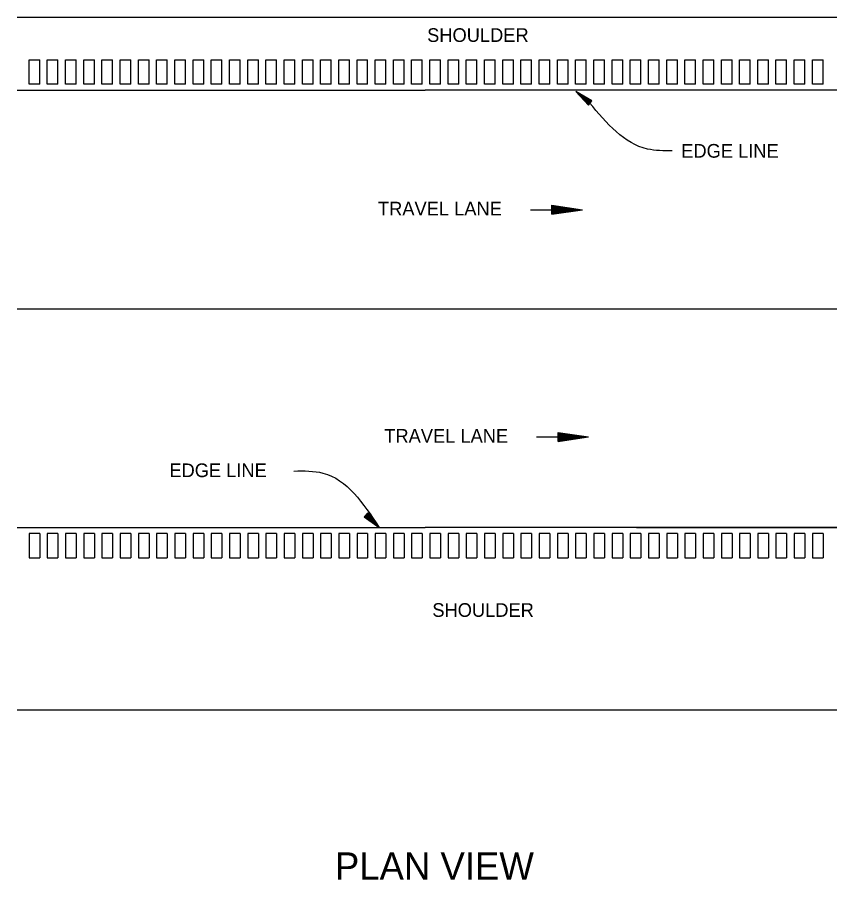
# Model space of a CAD drawing. Extents: x 1931522 to 1935523, y 600380 to 605075.
# Drawn here: x 1932731.4 to 1933091.3, y 600475.1 to 600853.7 of the extents above; entities that cross this region are included whole.
import ezdxf

# ---------------------------------------------------------------- set-up
doc = ezdxf.new("R2010")
doc.units = 0
doc.layers.add('Default', color=7, linetype='Continuous')

msp = doc.modelspace()

# ---------------------------------------------------------------- linework, layer by layer
at = {"layer": 'Default'}
for p, q in [((1932731.37, 600853.72), (1933091.26, 600853.72)), ((1932736.57, 600824.38), (1932736.57, 600835.02)), ((1932736.57, 600835.02), (1932741.25, 600835.02)), ((1932741.25, 600824.38), (1932741.25, 600835.02)), ((1932744.57, 600824.38), (1932744.57, 600835.02)), ((1932744.57, 600835.02), (1932749.25, 600835.02)), ((1932749.25, 600824.38), (1932749.25, 600835.02)), ((1932752.57, 600824.38), (1932752.57, 600835.02)), ((1932752.57, 600835.02), (1932757.25, 600835.02)), ((1932757.25, 600824.38), (1932757.25, 600835.02)), ((1932760.57, 600824.38), (1932760.57, 600835.02)), ((1932760.57, 600835.02), (1932765.25, 600835.02)), ((1932765.25, 600824.38), (1932765.25, 600835.02)), ((1932768.57, 600824.38), (1932768.57, 600835.02)), ((1932768.57, 600835.02), (1932773.25, 600835.02)), ((1932773.25, 600824.38), (1932773.25, 600835.02)), ((1932776.57, 600824.38), (1932776.57, 600835.02)), ((1932776.57, 600835.02), (1932781.25, 600835.02)), ((1932781.25, 600824.38), (1932781.25, 600835.02)), ((1932784.57, 600824.38), (1932784.57, 600835.02)), ((1932784.57, 600835.02), (1932789.25, 600835.02)), ((1932789.25, 600824.38), (1932789.25, 600835.02)), ((1932792.57, 600824.38), (1932792.57, 600835.02)), ((1932792.57, 600835.02), (1932797.25, 600835.02)), ((1932797.25, 600824.38), (1932797.25, 600835.02)), ((1932800.57, 600824.38), (1932800.57, 600835.02)), ((1932800.57, 600835.02), (1932805.25, 600835.02)), ((1932805.25, 600824.38), (1932805.25, 600835.02)), ((1932808.57, 600824.38), (1932808.57, 600835.02)), ((1932808.57, 600835.02), (1932813.25, 600835.02)), ((1932813.25, 600824.38), (1932813.25, 600835.02)), ((1932816.57, 600824.38), (1932816.57, 600835.02)), ((1932816.57, 600835.02), (1932821.26, 600835.02)), ((1932821.26, 600824.38), (1932821.26, 600835.02)), ((1932824.58, 600824.38), (1932824.58, 600835.02)), ((1932824.58, 600835.02), (1932829.26, 600835.02)), ((1932829.26, 600824.38), (1932829.26, 600835.02)), ((1932832.58, 600824.38), (1932832.58, 600835.02)), ((1932832.58, 600835.02), (1932837.26, 600835.02)), ((1932837.26, 600824.38), (1932837.26, 600835.02)), ((1932840.58, 600824.38), (1932840.58, 600835.02)), ((1932840.58, 600835.02), (1932845.26, 600835.02)), ((1932845.26, 600824.38), (1932845.26, 600835.02)), ((1932848.58, 600824.38), (1932848.58, 600835.02)), ((1932848.58, 600835.02), (1932853.26, 600835.02)), ((1932853.26, 600824.38), (1932853.26, 600835.02)), ((1932856.58, 600824.38), (1932856.58, 600835.02)), ((1932856.58, 600824.38), (1932856.58, 600835.02)), ((1932856.58, 600835.02), (1932861.26, 600835.02)), ((1932861.26, 600824.38), (1932861.26, 600835.02)), ((1932864.58, 600824.38), (1932864.58, 600835.02)), ((1932864.58, 600835.02), (1932869.26, 600835.02)), ((1932869.26, 600824.38), (1932869.26, 600835.02)), ((1932872.58, 600824.38), (1932872.58, 600835.02)), ((1932872.58, 600835.02), (1932877.26, 600835.02)), ((1932877.26, 600824.38), (1932877.26, 600835.02)), ((1932880.58, 600824.38), (1932880.58, 600835.02)), ((1932880.58, 600835.02), (1932885.26, 600835.02)), ((1932885.26, 600824.38), (1932885.26, 600835.02)), ((1932888.58, 600824.38), (1932888.58, 600835.02)), ((1932888.58, 600835.02), (1932893.26, 600835.02)), ((1932893.26, 600824.38), (1932893.26, 600835.02)), ((1932896.58, 600824.38), (1932896.58, 600835.02)), ((1932896.58, 600835.02), (1932901.26, 600835.02)), ((1932901.26, 600824.38), (1932901.26, 600835.02)), ((1932904.58, 600824.38), (1932904.58, 600835.02)), ((1932904.58, 600835.02), (1932909.26, 600835.02)), ((1932909.26, 600824.38), (1932909.26, 600835.02)), ((1932912.58, 600824.38), (1932912.58, 600835.02)), ((1932912.58, 600835.02), (1932917.26, 600835.02)), ((1932917.26, 600824.38), (1932917.26, 600835.02)), ((1932920.58, 600824.38), (1932920.58, 600835.02)), ((1932920.58, 600835.02), (1932925.26, 600835.02)), ((1932925.26, 600824.38), (1932925.26, 600835.02)), ((1932928.58, 600824.38), (1932928.58, 600835.02)), ((1932928.58, 600835.02), (1932933.26, 600835.02)), ((1932933.26, 600824.38), (1932933.26, 600835.02)), ((1932936.58, 600824.38), (1932936.58, 600835.02)), ((1932936.58, 600835.02), (1932941.26, 600835.02)), ((1932941.26, 600824.38), (1932941.26, 600835.02)), ((1932944.58, 600824.38), (1932944.58, 600835.02)), ((1932944.58, 600835.02), (1932949.26, 600835.02)), ((1932949.26, 600824.38), (1932949.26, 600835.02)), ((1932952.58, 600824.38), (1932952.58, 600835.02)), ((1932952.58, 600835.02), (1932957.26, 600835.02)), ((1932957.26, 600824.38), (1932957.26, 600835.02)), ((1932960.58, 600824.38), (1932960.58, 600835.02)), ((1932960.58, 600835.02), (1932965.26, 600835.02)), ((1932965.26, 600824.38), (1932965.26, 600835.02)), ((1932968.58, 600824.38), (1932968.58, 600835.02)), ((1932968.58, 600835.02), (1932973.26, 600835.02)), ((1932973.26, 600824.38), (1932973.26, 600835.02)), ((1932976.58, 600824.38), (1932976.58, 600835.02)), ((1932976.58, 600835.02), (1932981.26, 600835.02)), ((1932981.26, 600824.38), (1932981.26, 600835.02)), ((1932984.58, 600824.38), (1932984.58, 600835.02)), ((1932984.58, 600835.02), (1932989.26, 600835.02)), ((1932989.26, 600824.38), (1932989.26, 600835.02)), ((1932992.58, 600824.38), (1932992.58, 600835.02)), ((1932992.58, 600835.02), (1932997.26, 600835.02)), ((1932997.26, 600824.38), (1932997.26, 600835.02)), ((1933000.58, 600824.38), (1933000.58, 600835.02)), ((1933000.58, 600835.02), (1933005.26, 600835.02)), ((1933005.26, 600824.38), (1933005.26, 600835.02)), ((1933008.58, 600824.38), (1933008.58, 600835.02)), ((1933008.58, 600835.02), (1933013.26, 600835.02)), ((1933013.26, 600824.38), (1933013.26, 600835.02)), ((1933016.58, 600824.38), (1933016.58, 600835.02)), ((1933016.58, 600835.02), (1933021.26, 600835.02)), ((1933021.26, 600824.38), (1933021.26, 600835.02)), ((1933024.58, 600824.38), (1933024.58, 600835.02)), ((1933024.58, 600835.02), (1933029.26, 600835.02)), ((1933029.26, 600824.38), (1933029.26, 600835.02)), ((1933032.58, 600824.38), (1933032.58, 600835.02)), ((1933032.58, 600835.02), (1933037.26, 600835.02)), ((1933037.26, 600824.38), (1933037.26, 600835.02)), ((1933040.58, 600824.38), (1933040.58, 600835.02)), ((1933040.58, 600835.02), (1933045.26, 600835.02)), ((1933045.26, 600824.38), (1933045.26, 600835.02)), ((1933048.58, 600824.38), (1933048.58, 600835.02)), ((1933048.58, 600835.02), (1933053.26, 600835.02)), ((1933053.26, 600824.38), (1933053.26, 600835.02)), ((1933056.58, 600824.38), (1933056.58, 600835.02)), ((1933056.58, 600835.02), (1933061.26, 600835.02)), ((1933061.26, 600824.38), (1933061.26, 600835.02)), ((1933064.58, 600824.38), (1933064.58, 600835.02)), ((1933064.58, 600835.02), (1933069.26, 600835.02)), ((1933069.26, 600824.38), (1933069.26, 600835.02)), ((1933072.58, 600824.38), (1933072.58, 600835.02)), ((1933072.58, 600835.02), (1933077.26, 600835.02)), ((1933077.26, 600824.38), (1933077.26, 600835.02)), ((1933080.58, 600824.38), (1933080.58, 600835.02)), ((1933080.58, 600835.02), (1933085.26, 600835.02)), ((1933085.26, 600824.38), (1933085.26, 600835.02)), ((1932741.25, 600824.38), (1932736.57, 600824.38)), ((1932749.25, 600824.38), (1932744.57, 600824.38)), ((1932757.25, 600824.38), (1932752.57, 600824.38)), ((1932765.25, 600824.38), (1932760.57, 600824.38)), ((1932773.25, 600824.38), (1932768.57, 600824.38)), ((1932781.25, 600824.38), (1932776.57, 600824.38)), ((1932789.25, 600824.38), (1932784.57, 600824.38)), ((1932797.25, 600824.38), (1932792.57, 600824.38)), ((1932805.25, 600824.38), (1932800.57, 600824.38)), ((1932813.25, 600824.38), (1932808.57, 600824.38)), ((1932821.26, 600824.38), (1932816.57, 600824.38)), ((1932829.26, 600824.38), (1932824.58, 600824.38)), ((1932837.26, 600824.38), (1932832.58, 600824.38)), ((1932845.26, 600824.38), (1932840.58, 600824.38)), ((1932853.26, 600824.38), (1932848.58, 600824.38)), ((1932861.26, 600824.38), (1932856.58, 600824.38)), ((1932869.26, 600824.38), (1932864.58, 600824.38)), ((1932877.26, 600824.38), (1932872.58, 600824.38)), ((1932885.26, 600824.38), (1932880.58, 600824.38)), ((1932893.26, 600824.38), (1932888.58, 600824.38)), ((1932901.26, 600824.38), (1932896.58, 600824.38)), ((1932909.26, 600824.38), (1932904.58, 600824.38)), ((1932917.26, 600824.38), (1932912.58, 600824.38)), ((1932925.26, 600824.38), (1932920.58, 600824.38)), ((1932933.26, 600824.38), (1932928.58, 600824.38)), ((1932941.26, 600824.38), (1932936.58, 600824.38)), ((1932949.26, 600824.38), (1932944.58, 600824.38)), ((1932957.26, 600824.38), (1932952.58, 600824.38)), ((1932965.26, 600824.38), (1932960.58, 600824.38)), ((1932973.26, 600824.38), (1932968.58, 600824.38)), ((1932981.26, 600824.38), (1932976.58, 600824.38)), ((1932989.26, 600824.38), (1932984.58, 600824.38)), ((1932997.26, 600824.38), (1932992.58, 600824.38)), ((1933005.26, 600824.38), (1933000.58, 600824.38)), ((1933013.26, 600824.38), (1933008.58, 600824.38)), ((1933021.26, 600824.38), (1933016.58, 600824.38)), ((1933029.26, 600824.38), (1933024.58, 600824.38)), ((1933037.26, 600824.38), (1933032.58, 600824.38)), ((1933045.26, 600824.38), (1933040.58, 600824.38)), ((1933053.26, 600824.38), (1933048.58, 600824.38)), ((1933061.26, 600824.38), (1933056.58, 600824.38)), ((1933069.26, 600824.38), (1933064.58, 600824.38)), ((1933077.26, 600824.38), (1933072.58, 600824.38)), ((1933085.26, 600824.38), (1933080.58, 600824.38)), ((1932731.37, 600821.72), (1932910.48, 600821.72)), ((1933091.26, 600821.72), (1932910.48, 600821.72)), ((1932982.2, 600815.16), (1932976.7, 600821.1)), ((1932983.7, 600817.04), (1932976.7, 600821.1)), ((1932982.32, 600815.32), (1932977.74, 600820.26)), ((1932983.58, 600816.88), (1932977.74, 600820.26)), ((1932983.44, 600816.72), (1932978.82, 600819.42)), ((1932982.46, 600815.48), (1932978.82, 600819.42)), ((1932982.58, 600815.64), (1932979.86, 600818.58)), ((1932983.32, 600816.56), (1932979.86, 600818.58)), ((1932983.18, 600816.4), (1932980.92, 600817.72)), ((1932982.7, 600815.8), (1932980.92, 600817.72)), ((1932983.06, 600816.24), (1932981.96, 600816.9)), ((1932982.82, 600815.96), (1932981.96, 600816.9)), ((1932982.2, 600815.16), (1932983.7, 600817.04)), ((1932966.16, 600771.22), (1932979.6, 600769.24)), ((1932966.16, 600767.22), (1932966.16, 600771.22)), ((1932966.16, 600770.9), (1932977.36, 600769.24)), ((1932966.16, 600770.56), (1932975.06, 600769.24)), ((1932966.16, 600770.22), (1932972.84, 600769.24)), ((1932966.16, 600769.88), (1932970.54, 600769.24)), ((1932956.72, 600769.24), (1932979.6, 600769.24)), ((1932966.16, 600769.56), (1932968.3, 600769.24)), ((1932966.16, 600767.22), (1932979.6, 600769.24)), ((1932966.16, 600768.58), (1932970.54, 600769.24)), ((1932966.16, 600767.88), (1932975.06, 600769.24)), ((1932966.16, 600767.54), (1932977.36, 600769.24)), ((1932966.16, 600768.22), (1932972.84, 600769.24)), ((1932966.16, 600768.9), (1932968.3, 600769.24)), ((1932731.37, 600725.72), (1933091.26, 600725.72)), ((1932968.86, 600671.52), (1932982.3, 600669.54)), ((1932968.86, 600667.52), (1932968.86, 600671.52)), ((1932959.42, 600669.54), (1932982.3, 600669.54)), ((1932968.86, 600671.2), (1932980.06, 600669.54)), ((1932968.86, 600670.86), (1932977.76, 600669.54)), ((1932968.86, 600670.52), (1932975.54, 600669.54)), ((1932968.86, 600670.18), (1932973.24, 600669.54)), ((1932968.86, 600669.86), (1932971, 600669.54)), ((1932968.86, 600667.52), (1932982.3, 600669.54)), ((1932968.86, 600668.88), (1932973.24, 600669.54)), ((1932968.86, 600668.18), (1932977.76, 600669.54)), ((1932968.86, 600667.84), (1932980.06, 600669.54)), ((1932968.86, 600668.52), (1932975.54, 600669.54)), ((1932968.86, 600669.2), (1932971, 600669.54)), ((1932885.38, 600636.22), (1932883.72, 600634.5)), ((1932883.72, 600634.5), (1932890.3, 600629.78)), ((1932883.86, 600634.64), (1932889.34, 600630.72)), ((1932884, 600634.78), (1932888.34, 600631.68)), ((1932884.14, 600634.92), (1932887.4, 600632.6)), ((1932884.28, 600635.06), (1932886.42, 600633.54)), ((1932884.42, 600635.22), (1932885.46, 600634.48)), ((1932884.68, 600635.48), (1932885.46, 600634.48)), ((1932884.82, 600635.62), (1932886.42, 600633.54)), ((1932884.96, 600635.78), (1932887.4, 600632.6)), ((1932885.1, 600635.92), (1932888.34, 600631.68)), ((1932885.24, 600636.06), (1932889.34, 600630.72)), ((1932885.38, 600636.22), (1932890.3, 600629.78)), ((1932731.37, 600629.72), (1932910.48, 600629.72)), ((1933091.26, 600629.72), (1932910.48, 600629.72)), ((1933003.38, 600629.72), (1933091.26, 600629.72)), ((1932741.25, 600627.06), (1932736.57, 600627.06)), ((1932736.57, 600627.06), (1932736.57, 600616.42)), ((1932741.25, 600627.06), (1932741.25, 600616.42)), ((1932749.25, 600627.06), (1932744.57, 600627.06)), ((1932744.57, 600627.06), (1932744.57, 600616.42)), ((1932749.25, 600627.06), (1932749.25, 600616.42)), ((1932757.25, 600627.06), (1932752.57, 600627.06)), ((1932752.57, 600627.06), (1932752.57, 600616.42)), ((1932757.25, 600627.06), (1932757.25, 600616.42)), ((1932765.25, 600627.06), (1932760.57, 600627.06)), ((1932760.57, 600627.06), (1932760.57, 600616.42)), ((1932765.25, 600627.06), (1932765.25, 600616.42)), ((1932773.25, 600627.06), (1932768.57, 600627.06)), ((1932768.57, 600627.06), (1932768.57, 600616.42)), ((1932773.25, 600627.06), (1932773.25, 600616.42)), ((1932781.25, 600627.06), (1932776.57, 600627.06)), ((1932776.57, 600627.06), (1932776.57, 600616.42)), ((1932781.25, 600627.06), (1932781.25, 600616.42)), ((1932789.25, 600627.06), (1932784.57, 600627.06)), ((1932784.57, 600627.06), (1932784.57, 600616.42)), ((1932789.25, 600627.06), (1932789.25, 600616.42)), ((1932797.25, 600627.06), (1932792.57, 600627.06)), ((1932792.57, 600627.06), (1932792.57, 600616.42)), ((1932797.25, 600627.06), (1932797.25, 600616.42)), ((1932805.25, 600627.06), (1932800.57, 600627.06)), ((1932800.57, 600627.06), (1932800.57, 600616.42)), ((1932805.25, 600627.06), (1932805.25, 600616.42)), ((1932813.25, 600627.06), (1932808.57, 600627.06)), ((1932808.57, 600627.06), (1932808.57, 600616.42)), ((1932813.25, 600627.06), (1932813.25, 600616.42)), ((1932821.26, 600627.06), (1932816.57, 600627.06)), ((1932816.57, 600627.06), (1932816.57, 600616.42)), ((1932821.26, 600627.06), (1932821.26, 600616.42)), ((1932829.26, 600627.06), (1932824.58, 600627.06)), ((1932824.58, 600627.06), (1932824.58, 600616.42)), ((1932829.26, 600627.06), (1932829.26, 600616.42)), ((1932837.26, 600627.06), (1932832.58, 600627.06)), ((1932832.58, 600627.06), (1932832.58, 600616.42)), ((1932837.26, 600627.06), (1932837.26, 600616.42)), ((1932845.26, 600627.06), (1932840.58, 600627.06)), ((1932840.58, 600627.06), (1932840.58, 600616.42)), ((1932845.26, 600627.06), (1932845.26, 600616.42)), ((1932853.26, 600627.06), (1932848.58, 600627.06)), ((1932848.58, 600627.06), (1932848.58, 600616.42)), ((1932853.26, 600627.06), (1932853.26, 600616.42)), ((1932861.26, 600627.06), (1932856.58, 600627.06)), ((1932856.58, 600627.06), (1932856.58, 600616.42)), ((1932861.26, 600627.06), (1932861.26, 600616.42)), ((1932869.26, 600627.06), (1932864.58, 600627.06)), ((1932864.58, 600627.06), (1932864.58, 600616.42)), ((1932869.26, 600627.06), (1932869.26, 600616.42)), ((1932877.26, 600627.06), (1932872.58, 600627.06)), ((1932872.58, 600627.06), (1932872.58, 600616.42)), ((1932877.26, 600627.06), (1932877.26, 600616.42)), ((1932885.26, 600627.06), (1932880.58, 600627.06)), ((1932880.58, 600627.06), (1932880.58, 600616.42)), ((1932885.26, 600627.06), (1932885.26, 600616.42)), ((1932893.26, 600627.06), (1932888.58, 600627.06)), ((1932888.58, 600627.06), (1932888.58, 600616.42)), ((1932893.26, 600627.06), (1932893.26, 600616.42)), ((1932901.26, 600627.06), (1932896.58, 600627.06)), ((1932896.58, 600627.06), (1932896.58, 600616.42)), ((1932901.26, 600627.06), (1932901.26, 600616.42)), ((1932909.26, 600627.06), (1932904.58, 600627.06)), ((1932904.58, 600627.06), (1932904.58, 600616.42)), ((1932909.26, 600627.06), (1932909.26, 600616.42)), ((1932917.26, 600627.06), (1932912.58, 600627.06)), ((1932912.58, 600627.06), (1932912.58, 600616.42)), ((1932917.26, 600627.06), (1932917.26, 600616.42)), ((1932925.26, 600627.06), (1932920.58, 600627.06)), ((1932920.58, 600627.06), (1932920.58, 600616.42)), ((1932925.26, 600627.06), (1932925.26, 600616.42)), ((1932933.26, 600627.06), (1932928.58, 600627.06)), ((1932928.58, 600627.06), (1932928.58, 600616.42)), ((1932933.26, 600627.06), (1932933.26, 600616.42)), ((1932941.26, 600627.06), (1932936.58, 600627.06)), ((1932936.58, 600627.06), (1932936.58, 600616.42)), ((1932941.26, 600627.06), (1932941.26, 600616.42)), ((1932949.26, 600627.06), (1932944.58, 600627.06)), ((1932944.58, 600627.06), (1932944.58, 600616.42)), ((1932949.26, 600627.06), (1932949.26, 600616.42)), ((1932957.26, 600627.06), (1932952.58, 600627.06)), ((1932952.58, 600627.06), (1932952.58, 600616.42)), ((1932957.26, 600627.06), (1932957.26, 600616.42)), ((1932965.26, 600627.06), (1932960.58, 600627.06)), ((1932960.58, 600627.06), (1932960.58, 600616.42)), ((1932965.26, 600627.06), (1932965.26, 600616.42)), ((1932973.26, 600627.06), (1932968.58, 600627.06)), ((1932968.58, 600627.06), (1932968.58, 600616.42)), ((1932973.26, 600627.06), (1932973.26, 600616.42)), ((1932981.26, 600627.06), (1932976.58, 600627.06)), ((1932976.58, 600627.06), (1932976.58, 600616.42)), ((1932981.26, 600627.06), (1932981.26, 600616.42)), ((1932989.26, 600627.06), (1932984.58, 600627.06)), ((1932984.58, 600627.06), (1932984.58, 600616.42)), ((1932989.26, 600627.06), (1932989.26, 600616.42)), ((1932997.26, 600627.06), (1932992.58, 600627.06)), ((1932992.58, 600627.06), (1932992.58, 600616.42)), ((1932997.26, 600627.06), (1932997.26, 600616.42)), ((1933005.26, 600627.06), (1933000.58, 600627.06)), ((1933000.58, 600627.06), (1933000.58, 600616.42)), ((1933005.26, 600627.06), (1933005.26, 600616.42)), ((1933013.26, 600627.06), (1933008.58, 600627.06)), ((1933008.58, 600627.06), (1933008.58, 600616.42)), ((1933013.26, 600627.06), (1933013.26, 600616.42)), ((1933021.26, 600627.06), (1933016.58, 600627.06)), ((1933016.58, 600627.06), (1933016.58, 600616.42)), ((1933021.26, 600627.06), (1933021.26, 600616.42)), ((1933029.26, 600627.06), (1933024.58, 600627.06)), ((1933024.58, 600627.06), (1933024.58, 600616.42)), ((1933029.26, 600627.06), (1933029.26, 600616.42)), ((1933037.26, 600627.06), (1933032.58, 600627.06)), ((1933032.58, 600627.06), (1933032.58, 600616.42)), ((1933037.26, 600627.06), (1933037.26, 600616.42)), ((1933045.26, 600627.06), (1933040.58, 600627.06)), ((1933040.58, 600627.06), (1933040.58, 600616.42)), ((1933045.26, 600627.06), (1933045.26, 600616.42)), ((1933053.26, 600627.06), (1933048.58, 600627.06)), ((1933048.58, 600627.06), (1933048.58, 600616.42)), ((1933053.26, 600627.06), (1933053.26, 600616.42)), ((1933061.26, 600627.06), (1933056.58, 600627.06)), ((1933056.58, 600627.06), (1933056.58, 600616.42)), ((1933061.26, 600627.06), (1933061.26, 600616.42)), ((1933069.26, 600627.06), (1933064.58, 600627.06)), ((1933064.58, 600627.06), (1933064.58, 600616.42)), ((1933069.26, 600627.06), (1933069.26, 600616.42)), ((1933077.26, 600627.06), (1933072.58, 600627.06)), ((1933072.58, 600627.06), (1933072.58, 600616.42)), ((1933077.26, 600627.06), (1933077.26, 600616.42)), ((1933085.26, 600627.06), (1933080.58, 600627.06)), ((1933080.58, 600627.06), (1933080.58, 600616.42)), ((1933085.26, 600627.06), (1933085.26, 600616.42)), ((1932736.57, 600616.42), (1932741.25, 600616.42)), ((1932744.57, 600616.42), (1932749.25, 600616.42)), ((1932752.57, 600616.42), (1932757.25, 600616.42)), ((1932760.57, 600616.42), (1932765.25, 600616.42)), ((1932768.57, 600616.42), (1932773.25, 600616.42)), ((1932776.57, 600616.42), (1932781.25, 600616.42)), ((1932784.57, 600616.42), (1932789.25, 600616.42)), ((1932792.57, 600616.42), (1932797.25, 600616.42)), ((1932800.57, 600616.42), (1932805.25, 600616.42)), ((1932808.57, 600616.42), (1932813.25, 600616.42)), ((1932816.57, 600616.42), (1932821.26, 600616.42)), ((1932824.58, 600616.42), (1932829.26, 600616.42)), ((1932832.58, 600616.42), (1932837.26, 600616.42)), ((1932840.58, 600616.42), (1932845.26, 600616.42)), ((1932848.58, 600616.42), (1932853.26, 600616.42)), ((1932856.58, 600616.42), (1932861.26, 600616.42)), ((1932864.58, 600616.42), (1932869.26, 600616.42)), ((1932872.58, 600616.42), (1932877.26, 600616.42)), ((1932880.58, 600616.42), (1932885.26, 600616.42)), ((1932888.58, 600616.42), (1932893.26, 600616.42)), ((1932896.58, 600616.42), (1932901.26, 600616.42)), ((1932904.58, 600616.42), (1932909.26, 600616.42)), ((1932912.58, 600616.42), (1932917.26, 600616.42)), ((1932920.58, 600616.42), (1932925.26, 600616.42)), ((1932928.58, 600616.42), (1932933.26, 600616.42)), ((1932936.58, 600616.42), (1932941.26, 600616.42)), ((1932944.58, 600616.42), (1932949.26, 600616.42)), ((1932952.58, 600616.42), (1932957.26, 600616.42)), ((1932960.58, 600616.42), (1932965.26, 600616.42)), ((1932968.58, 600616.42), (1932973.26, 600616.42)), ((1932976.58, 600616.42), (1932981.26, 600616.42)), ((1932984.58, 600616.42), (1932989.26, 600616.42)), ((1932992.58, 600616.42), (1932997.26, 600616.42)), ((1933000.58, 600616.42), (1933005.26, 600616.42)), ((1933008.58, 600616.42), (1933013.26, 600616.42)), ((1933016.58, 600616.42), (1933021.26, 600616.42)), ((1933024.58, 600616.42), (1933029.26, 600616.42)), ((1933032.58, 600616.42), (1933037.26, 600616.42)), ((1933040.58, 600616.42), (1933045.26, 600616.42)), ((1933048.58, 600616.42), (1933053.26, 600616.42)), ((1933056.58, 600616.42), (1933061.26, 600616.42)), ((1933064.58, 600616.42), (1933069.26, 600616.42)), ((1933072.58, 600616.42), (1933077.26, 600616.42)), ((1933080.58, 600616.42), (1933085.26, 600616.42)), ((1932731.37, 600549.71), (1933091.26, 600549.71))]:
    msp.add_line(p, q, dxfattribs=at)
for points in [[(1933018.98, 600795.1), (1933008.14, 600795.88), (1932982.66, 600816.18)], [(1932852.9, 600654.54), (1932865.64, 600653.66), (1932890.3, 600629.78)]]:
    msp.add_spline(points, degree=3, dxfattribs=at)

# ---------------------------------------------------------------- texts
for s, height, p in [('SHOULDER', 6, (1932911.38, 600842.9)), ('EDGE LINE', 6, (1933022.96, 600792.08)), ('TRAVEL LANE', 6.0002, (1932889.79, 600766.72)), ('TRAVEL LANE', 6.0002, (1932892.56, 600666.98)), ('EDGE LINE', 6, (1932798.18, 600651.86)), ('SHOULDER', 6, (1932913.66, 600590.53)), ('PLAN VIEW ', 12, (1932870.86, 600475.13))]:
    msp.add_text(s, height=height, dxfattribs=at).set_placement(p)

doc.saveas('drawing.dxf')
